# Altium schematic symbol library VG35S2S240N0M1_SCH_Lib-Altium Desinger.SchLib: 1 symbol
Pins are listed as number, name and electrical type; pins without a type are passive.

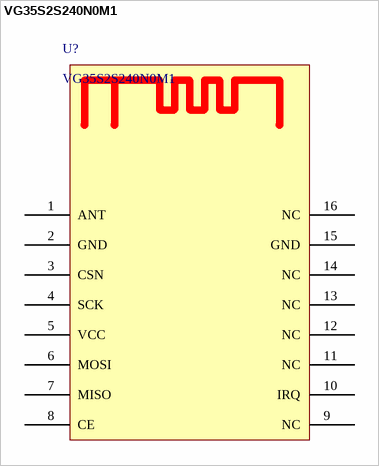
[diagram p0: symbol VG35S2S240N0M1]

## VG35S2S240N0M1
designator U?
pins: 1 ANT, 2 GND, 3 CSN, 4 SCK, 5 VCC, 6 MOSI, 7 MISO, 8 CE, 9 NC, 10 IRQ, 11 NC, 12 NC, 13 NC, 14 NC, 15 GND, 16 NC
